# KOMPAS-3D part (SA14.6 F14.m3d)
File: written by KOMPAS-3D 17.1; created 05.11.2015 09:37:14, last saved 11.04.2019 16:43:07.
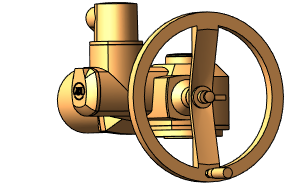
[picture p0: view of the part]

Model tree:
1. Операция без истории:7  (labels: Сталь 20  ГОСТ 1050-88)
